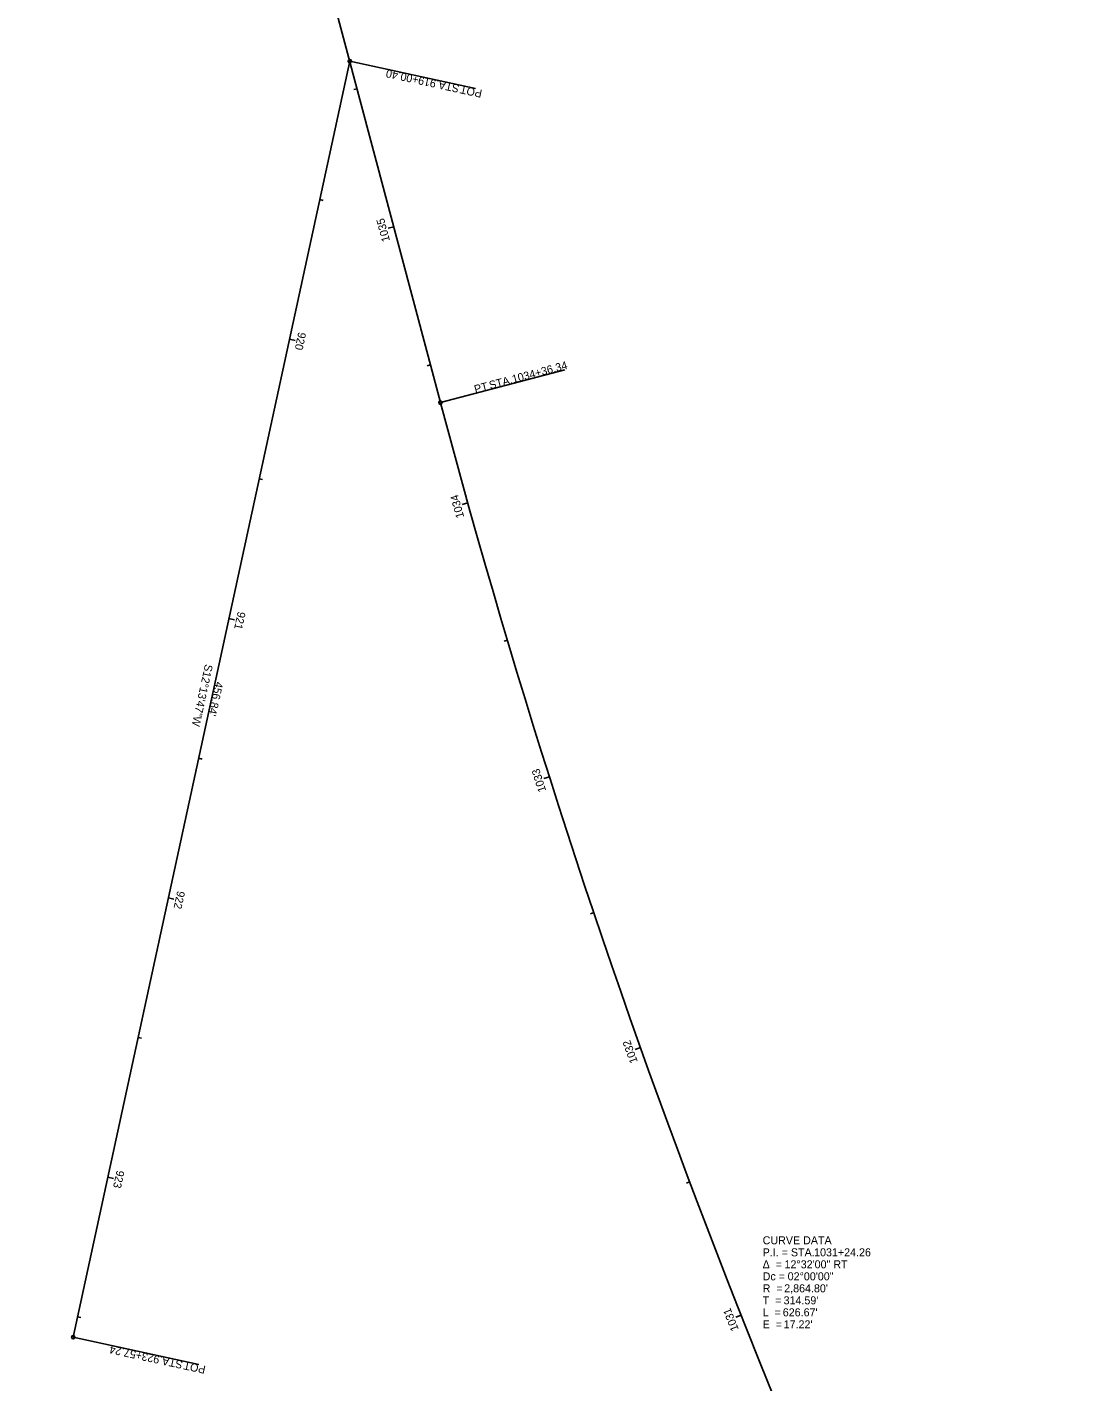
# Model space of a CAD drawing. Extents: x 2047708 to 2048167, y 281089 to 282219.
# Drawn here: x 2047755.5 to 2048125.7, y 281330.6 to 281804.6 of the extents above; entities that cross this region are included whole.
import ezdxf

# ---------------------------------------------------------------- set-up
doc = ezdxf.new("R2010")
doc.units = 0
for name, color, linetype in [('DR_X_Erosion_Control', 7, 'Continuous'), ('SV_X_Control_Cells_Found', 7, 'Continuous'), ('SV_X_Random_Point', 7, 'Continuous'), ('SV_X_Shot_Marker', 7, 'Continuous'), ('SV_X_Top_of_Bank', 7, 'Continuous'), ('UT_X_Telecom_Cells', 7, 'Continuous')]:
    doc.layers.add(name, color=color, linetype=linetype)

msp = doc.modelspace()

# ---------------------------------------------------------------- linework, layer by layer
at = {"layer": 'SV_X_Control_Cells_Found'}
for p, q in [((2047900.13, 281673.22), (2047755.49, 282218)), ((2047868.4, 281792.73), (2047771.63, 281346.26))]:
    msp.add_line(p, q, dxfattribs=at)
msp.add_arc((2050669, 282408.39), 2864.8, 194.86975, 207.40308, dxfattribs=at)
at = {"layer": 'SV_X_Random_Point'}
for p, q in [((2047868.4, 281792.73), (2047912.38, 281783.2)), ((2047900.13, 281673.22), (2047943.63, 281684.76)), ((2047771.63, 281346.26), (2047815.61, 281336.73))]:
    msp.add_line(p, q, dxfattribs=at)
for centre in [(2047868.4, 281792.73), (2047900.13, 281673.22), (2047771.63, 281346.26)]:
    msp.add_circle(centre, 0.6, dxfattribs=at)
at = {"layer": 'SV_X_Top_of_Bank'}
for p, q in [((2047870.97, 281783.07), (2047869.81, 281782.76)), ((2047857.89, 281744.26), (2047859.07, 281744.01)), ((2047883.8, 281734.74), (2047881.86, 281734.23)), ((2047847.3, 281695.39), (2047849.26, 281694.97)), ((2047896.63, 281686.42), (2047895.47, 281686.11)), ((2047836.71, 281646.53), (2047837.88, 281646.28)), ((2047909.68, 281638.15), (2047907.76, 281637.61)), ((2047826.12, 281597.66), (2047828.07, 281597.24)), ((2047923.54, 281590.11), (2047922.39, 281589.77)), ((2047815.53, 281548.8), (2047816.7, 281548.54)), ((2047938.24, 281542.32), (2047936.34, 281541.72)), ((2047804.94, 281499.93), (2047806.89, 281499.51)), ((2047953.77, 281494.8), (2047952.64, 281494.41)), ((2047794.34, 281451.07), (2047795.52, 281450.81)), ((2047970.13, 281447.55), (2047968.25, 281446.88)), ((2047783.75, 281402.2), (2047785.71, 281401.78)), ((2047987.31, 281400.59), (2047986.19, 281400.17)), ((2047773.16, 281353.34), (2047774.33, 281353.08)), ((2048005.31, 281353.95), (2048003.45, 281353.21))]:
    msp.add_line(p, q, dxfattribs=at)

# ---------------------------------------------------------------- texts
at = {"layer": 'DR_X_Erosion_Control'}
msp.add_text("456.84'", height=2.8, rotation=257.7703, dxfattribs=at).set_placement((2047821.41, 281575.78))
at = {"layer": 'SV_X_Random_Point'}
for s, rotation, p in [('919+00.40', 167.7703, (2047898.83, 281786.1)), (' STA. ', 167.7703, (2047907.95, 281784.13)), ('POT', 167.7703, (2047914.91, 281782.61)), ('1034+36.34', 14.8697, (2047925.58, 281680.01)), ('PT', 14.8697, (2047912.36, 281676.5)), (' STA. ', 14.8697, (2047916.56, 281677.62)), ('923+57.24', 167.7703, (2047802.07, 281339.62)), (' STA. ', 167.7703, (2047811.18, 281337.65)), ('POT', 167.7703, (2047818.15, 281336.14))]:
    msp.add_text(s, height=2.8, rotation=rotation, dxfattribs=at).set_placement(p)
at = {"layer": 'SV_X_Shot_Marker'}
msp.add_text('S12°13\'47"W', height=2.8, rotation=257.7703, dxfattribs=at).set_placement((2047817.78, 281581.87))
at = {"layer": 'SV_X_Top_of_Bank'}
for s, rotation, p in [('1035', 104.8697, (2047882.49, 281729.92)), ('920', 257.7703, (2047850.44, 281698.06)), ('1034', 105.5965, (2047908.46, 281633.25)), ('921', 257.7703, (2047829.24, 281600.28)), ('1033', 107.5965, (2047937.17, 281537.45)), ('922', 257.7703, (2047808.06, 281502.54)), ('1032', 109.5965, (2047969.23, 281442.63)), ('923', 257.7703, (2047786.87, 281404.8)), ('1031', 111.5965, (2048004.58, 281348.99))]:
    msp.add_text(s, height=2.8, rotation=rotation, dxfattribs=at).set_placement(p)
at = {"layer": 'UT_X_Telecom_Cells'}
for s, p in [('CURVE DATA', (2048012.89, 281378.74)), ('P.I. = STA. ', (2048012.89, 281374.54)), ('1031+24.26', (2048030.89, 281374.54)), ('Δ  = ', (2048012.89, 281370.34)), ('12°32\'00" RT', (2048020.54, 281370.34)), ('Dc = ', (2048012.89, 281366.14)), ('02°00\'00"', (2048021.64, 281366.14)), ('R  = ', (2048012.89, 281361.94)), ("2,864.80'", (2048020.43, 281361.94)), ('T  = ', (2048012.89, 281357.74)), ("314.59'", (2048020.21, 281357.74)), ('L  = ', (2048012.89, 281353.54)), ("626.67'", (2048019.93, 281353.54)), ('E  = ', (2048012.89, 281349.34)), ("17.22'", (2048020.24, 281349.34))]:
    msp.add_text(s, height=2.8, dxfattribs=at).set_placement(p)

doc.saveas('drawing.dxf')
